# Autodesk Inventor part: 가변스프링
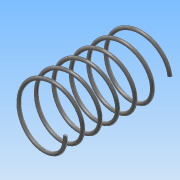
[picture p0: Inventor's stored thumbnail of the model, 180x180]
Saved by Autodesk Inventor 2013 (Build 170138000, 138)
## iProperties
Created: 2016-12
Part Number: 가변스프링
Material: 스테인리스강
Document SubType Name: Modeling
Designer: Administrator
Density: 8.08 g/cm^3
Mass: 1.90732 g
Surface Area: 9.48706 cm^2
Volume: 0.236055 cm^3
Author: Administrator
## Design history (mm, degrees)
sketch "스케치1"
  geometry: L1 (0, 0)-(8, 0); L2 (8, 0)-(8, 30.5); L3 (8, 30.5)-(0, 30.5); L4 (0, 30.5)-(0, 0); C1 r 0.5 at (8, 0)
  constraints: 8 end point, 2 parallel, 1 centre point, 1 coincident, 1 horizontal, 1 perpendicular
  dimensions: "d0" = 1 diameter of C1; "d1" = 16 diameter of L2 L4; "d2" = 30.49998 distance of L1.end L2.end (derived)
feature "코일1" sketch "스케치1" pitch "d3" = 10; turns "d5" = 6; dims "d4" = 30.49998 (= d2), "d6" = 0, angle "d7" = 90 deg, angle "d8" = 90 deg, "d9" = 0, "d10" = 0
sketch "스케치2"
  geometry: L1 (-15, 35)-(15, 35); L2 (15, 35)-(15, 0); L3 (15, 0)-(-15, 0); L4 (-15, 0)-(-15, 35); 2 further points
  constraints: 8 end point, 2 midpoint, 2 parallel, 1 coincident, 1 horizontal, 1 perpendicular
  dimensions: "d11" = 35 distance of L1.end L2.end (derived); "d13" = 30 distance of L1.start L1.end
extrude "돌출1" sketch "스케치2" stored distance "d14" = 50; taper "d15" = 0 deg
node "솔리드1"
